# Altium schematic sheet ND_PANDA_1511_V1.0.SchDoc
size A4
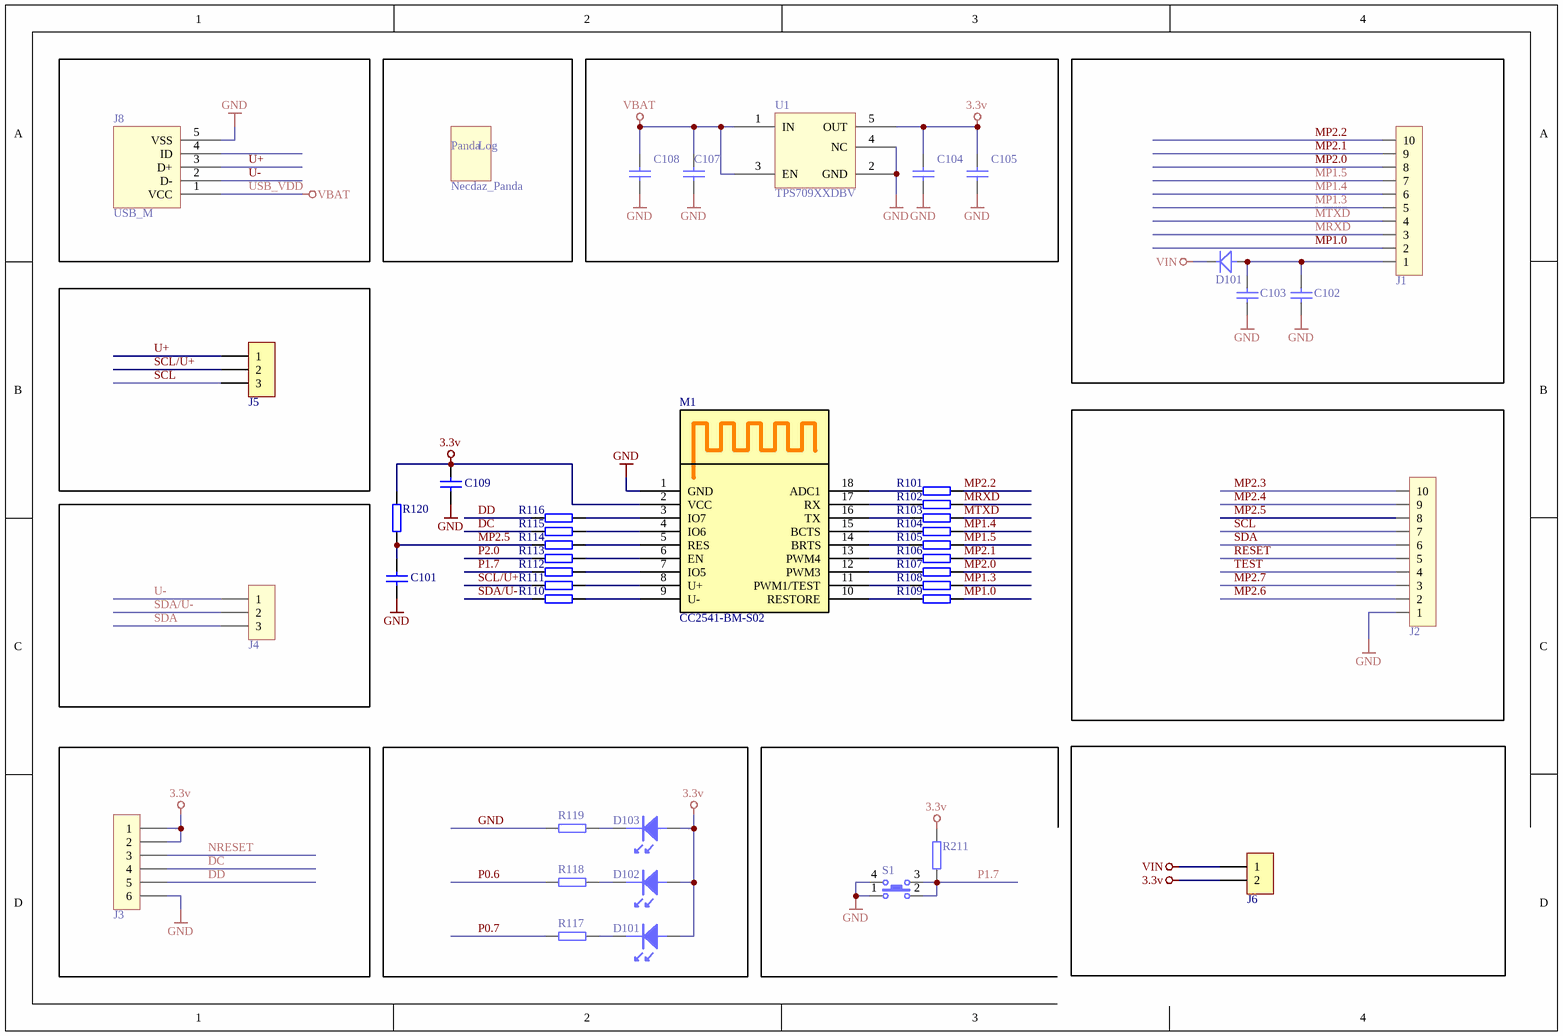
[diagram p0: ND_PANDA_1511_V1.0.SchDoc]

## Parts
(Parts that share a designator on the sheet are numbered #1, #2 ... from top to bottom, then left to right.)
C101  0.1uF  [CAP_SMD_0603]  (value not drawn)
C102  1uF  [CAP_SMD_0603]  (value not drawn)
C103  0.1uF  [CAP_SMD_0603]  (value not drawn)
C104  0.1uF  [CAP_SMD_0603]  (value not drawn)
C105  0.1uF  [CAP_SMD_0603]  (value not drawn)
C107  0.1uF  [CAP_SMD_0603]  (value not drawn)
C108  0.1uF  [CAP_SMD_0603]  (value not drawn)
C109  0.1uF  [CAP_SMD_0603]  (value not drawn)
D101#1  Diode  (value not drawn)
D101#2  LED  [LED_0603_RED]  (value not drawn)
D102  LED  [LED_0603_BLUE]  (value not drawn)
D103  LED  [LED_0603_GREEN]  (value not drawn)
J1  HDR1x10_2.54  [HDR2R54_180_1X10F]  (value not drawn)
J2  HDR1x10_2.54  [HDR2R54_180_1X10F]  (value not drawn)
J3  CON6  [HDR2R54_180_1X6M]  (value not drawn)
J4  CON3  [HDR_2R54_180M_1X3DP]  (value not drawn)
J5  CON3  [HDR_2R54_180M_1X3DP]  (value not drawn)
J6  CON2  [HDR2R54_180_1X2M]  (value not drawn)
J8  USB_M  [USB_Micro]
Log  Necdaz_Panda  [Necdaz_Panda]
M1  CC2541-BM-S02  [[18]BM-S02]
R101  1k  [RES_SMD_0603]  (value not drawn)
R102  1k  [RES_SMD_0603]  (value not drawn)
R103  1k  [RES_SMD_0603]  (value not drawn)
R104  1k  [RES_SMD_0603]  (value not drawn)
R105  1k  [RES_SMD_0603]  (value not drawn)
R106  1k  [RES_SMD_0603]  (value not drawn)
R107  1k  [RES_SMD_0603]  (value not drawn)
R108  1k  [RES_SMD_0603]  (value not drawn)
R109  1k  [RES_SMD_0603]  (value not drawn)
R110  1k  [RES_SMD_0603]  (value not drawn)
R111  1k  [RES_SMD_0603]  (value not drawn)
R112  1k  [RES_SMD_0603]  (value not drawn)
R113  1k  [RES_SMD_0603]  (value not drawn)
R114  1k  [RES_SMD_0603]  (value not drawn)
R115  1k  [RES_SMD_0603]  (value not drawn)
R116  1k  [RES_SMD_0603]  (value not drawn)
R117  20k  [RES_SMD_0603]  (value not drawn)
R118  20k  [RES_SMD_0603]  (value not drawn)
R119  330R  [RES_SMD_0603]  (value not drawn)
R120  20k  [RES_SMD_0603]  (value not drawn)
R211  20k  [RES_SMD_0603]  (value not drawn)
S1  SWITCH  [SW_PB4_B1]  (value not drawn)
U1  TPS709XXDBV  [SOT23-5A]

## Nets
3.3v: C104.2 C105.2 C109.2 D101#2.1 D102.1 D103.1 J3.1 J3.2 J6.2 M1.2(VCC) R120.2 R211.2 U1.5(OUT)
GND: C101.1 C102.1 C103.1 C104.1 C105.1 C107.1 C108.1 C109.1 J2.1 J3.6 J8.5(VSS) M1.1(GND) R119.2 S1.1 S1.4 U1.2(GND) U1.4(NC)
USB_VDD: C107.2 C108.2 J8.1(VCC) U1.1(IN) U1.3(EN)  [also labelled VBAT]
VIN: D101#1.2 J6.1
DC: J3.4 R115.2
DD: J3.5 R116.2
MP1.0: J1.2 R109.2
MP1.3: J1.5 R108.2
MP1.4: J1.6 R104.2
MP1.5: J1.7 R105.2
MP2.0: J1.8 R107.2
MP2.1: J1.9 R106.2
MP2.2: J1.10 R101.2
MP2.3: J2.10
MP2.4: J2.9
MP2.5: C101.2 J2.8 R114.1 R120.1
MP2.6: J2.2
MP2.7: J2.3
MRXD: J1.3 R102.2
MTXD: J1.4 R103.2
NRESET: J3.3
P0.6: R118.2
P0.7: R117.2
P1.7: R112.2 R211.1 S1.2 S1.3
P2.0: R113.1
RESET: J2.5
SCL: J2.7 J5.3
SCL/U+: J5.2 R111.2
SDA: J2.6 J4.3
SDA/U-: J4.2 R110.2
TEST: J2.4
U+: J5.1 J8.3(D+)
U-: J4.1 J8.2(D-)
NetC102_2: C102.2 C103.2 D101#1.1 J1.1
NetD101#2_2: D101#2.2 R117.1
NetD102_2: D102.2 R118.1
NetD103_2: D103.2 R119.1
NetM1_3: M1.3(IO7) R116.1
NetM1_4: M1.4(IO6) R115.1
NetM1_5: M1.5(RES) R114.2
NetM1_6: M1.6(EN) R113.2
NetM1_7: M1.7(IO5) R112.1
NetM1_8: M1.8(U+) R111.1
NetM1_9: M1.9(U-) R110.1
NetM1_10: M1.10(RESTORE) R109.1
NetM1_11: M1.11(PWM1/TEST) R108.1
NetM1_12: M1.12(PWM3) R107.1
NetM1_13: M1.13(PWM4) R106.1
NetM1_14: M1.14(BRTS) R105.1
NetM1_15: M1.15(BCTS) R104.1
NetM1_16: M1.16(TX) R103.1
NetM1_17: M1.17(RX) R102.1
NetM1_18: M1.18(ADC1) R101.1

Not connected (* = marked no-connect by the designer): J8 4(ID)

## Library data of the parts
C101-C105 C107-C109 = CAP
J1 J2 = HDR1x10_2.54: Header
J3 = CON6: Connector
J4 J5 = CON3: Connector
J6 = CON2: Connector
J8 = USB_M: MicroUSB接口
R101-R120 R211 = RES2: Resistor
